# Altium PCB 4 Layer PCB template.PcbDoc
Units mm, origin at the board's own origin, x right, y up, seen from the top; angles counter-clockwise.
Board outline 100 x 100 mm, 4 copper layers (Top, Plane 1, Plane 2, Bottom), stack 1.506 mm thick; 2 components, 0 nets, 4 pads, 0 vias.
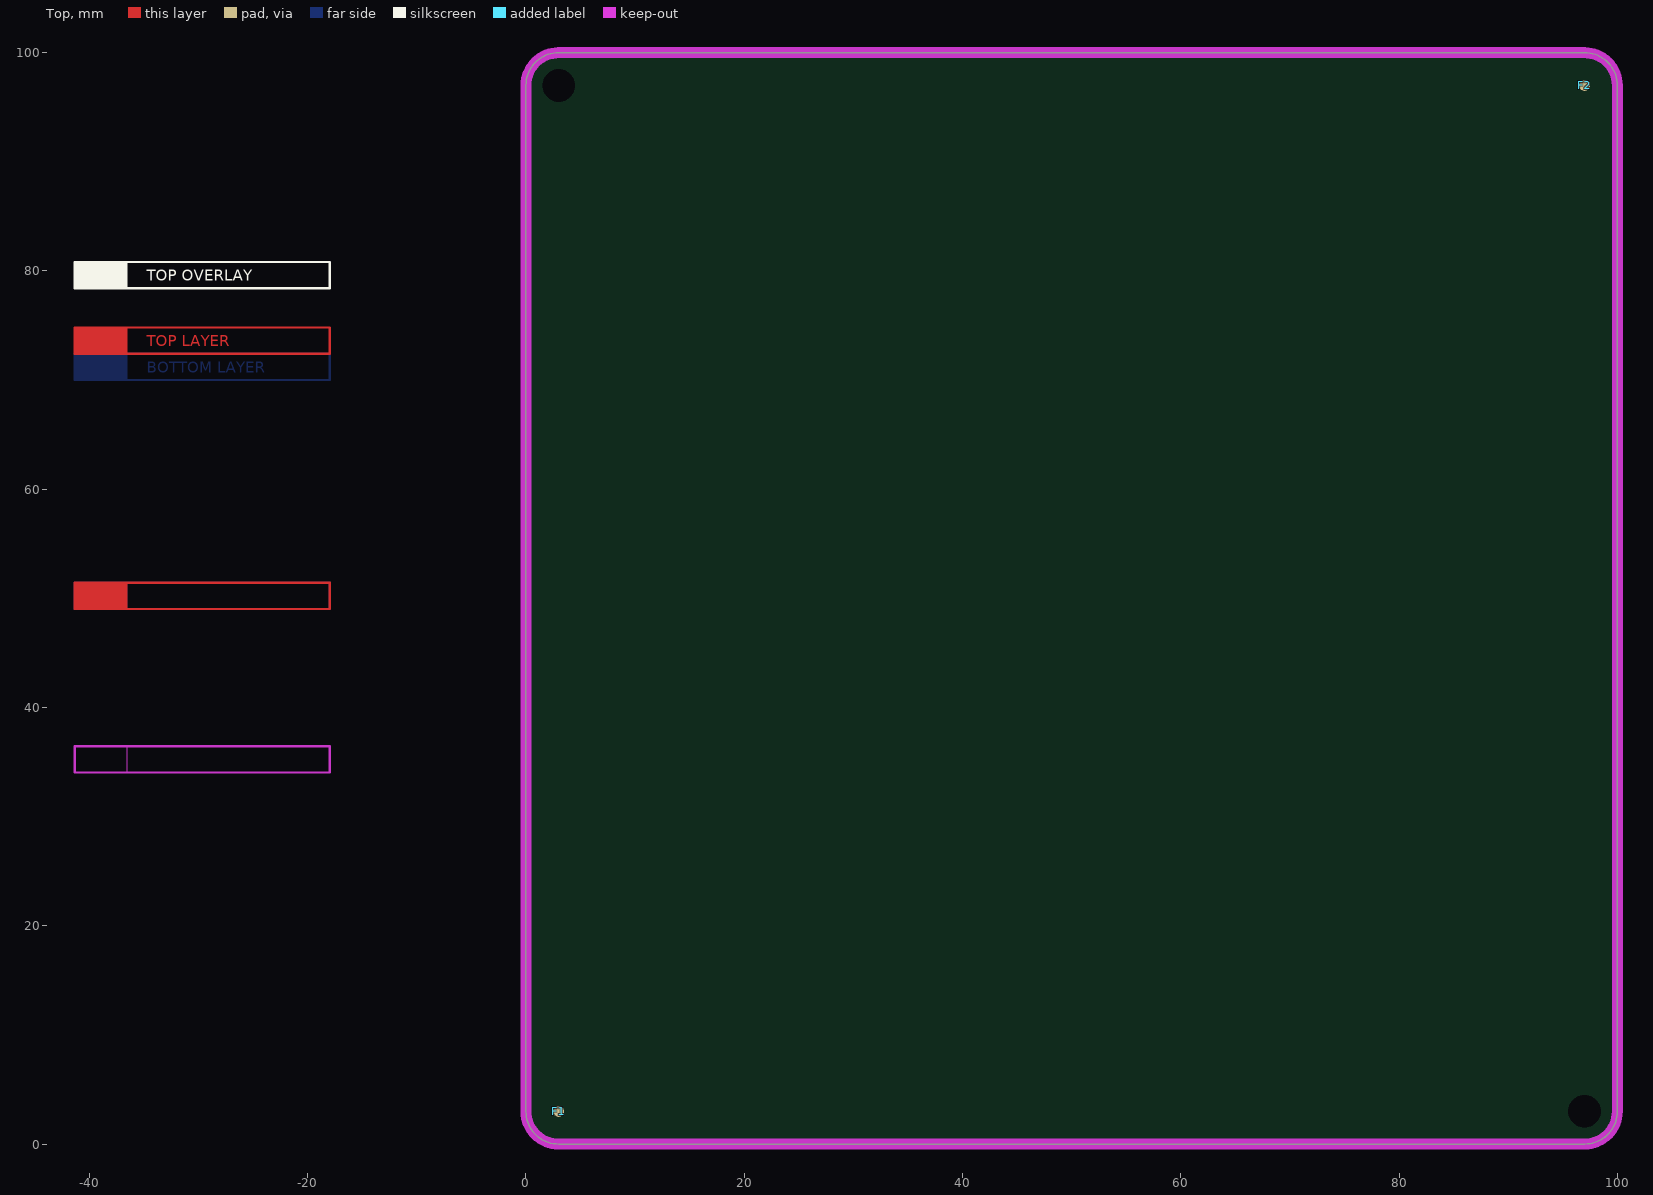
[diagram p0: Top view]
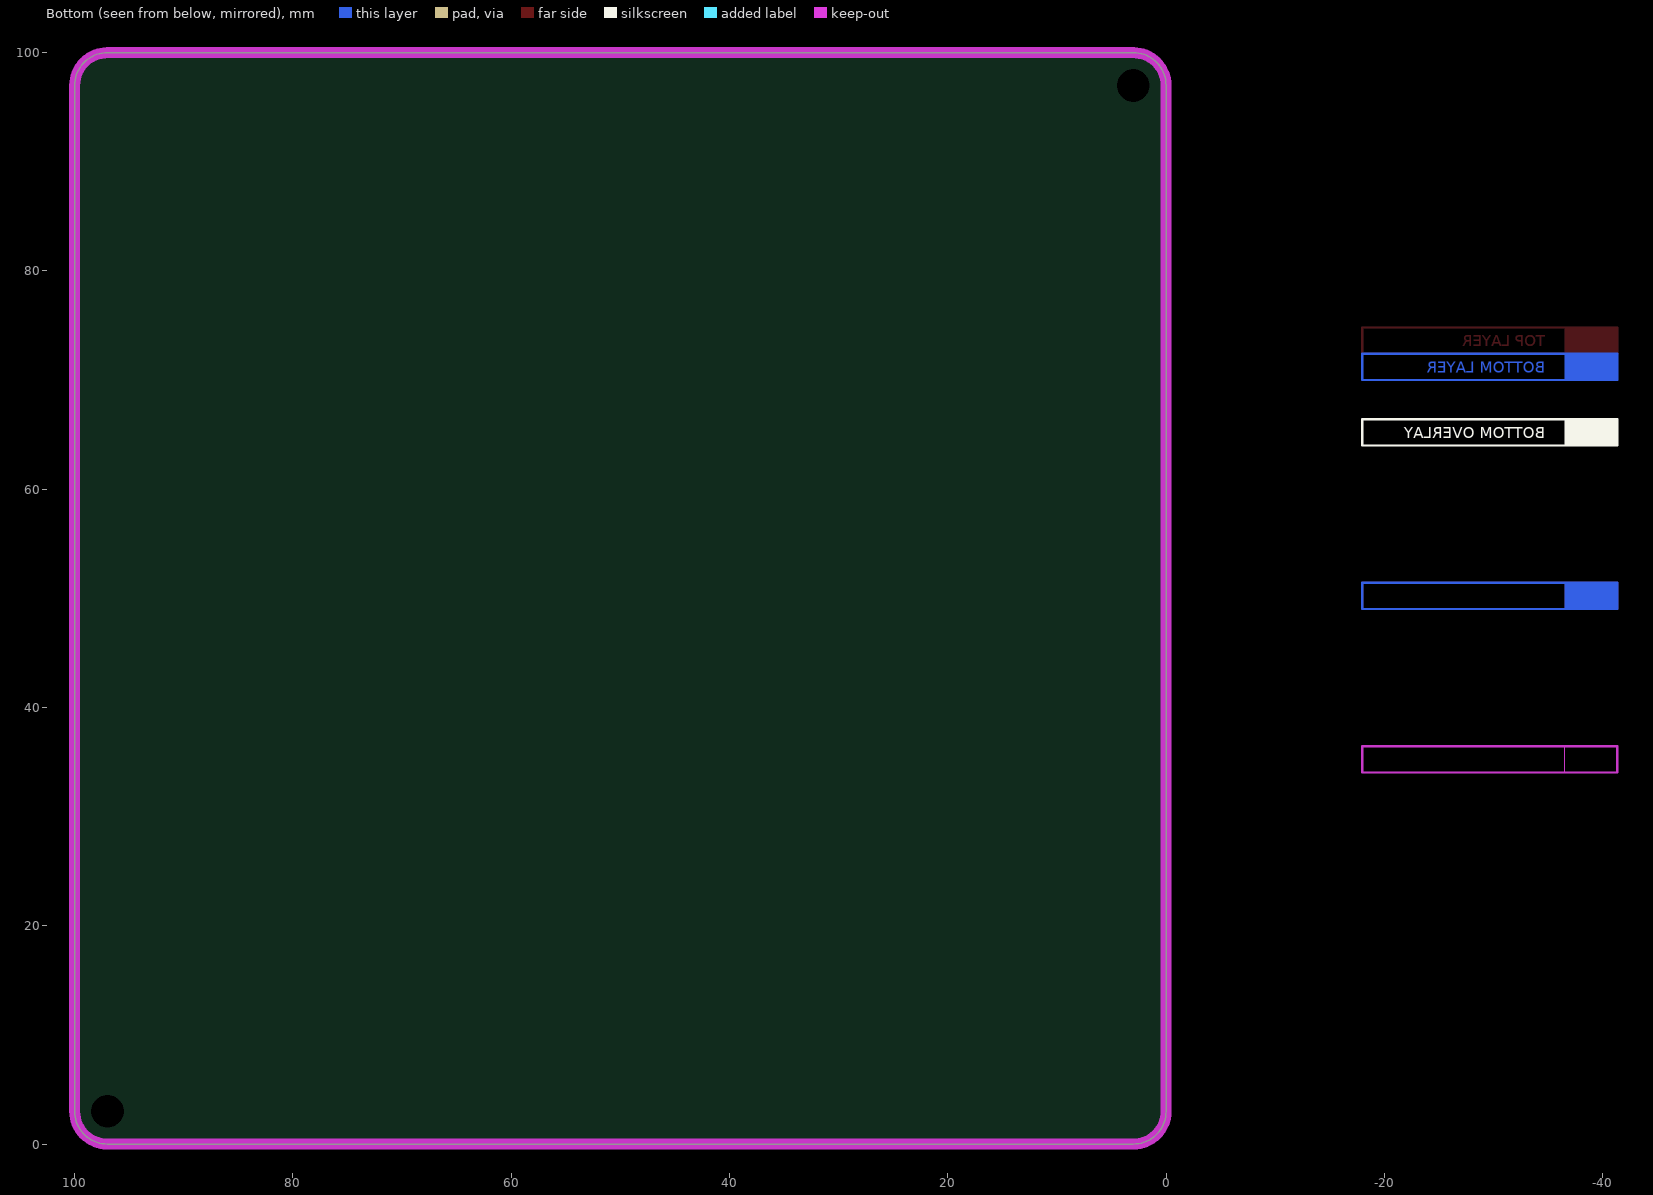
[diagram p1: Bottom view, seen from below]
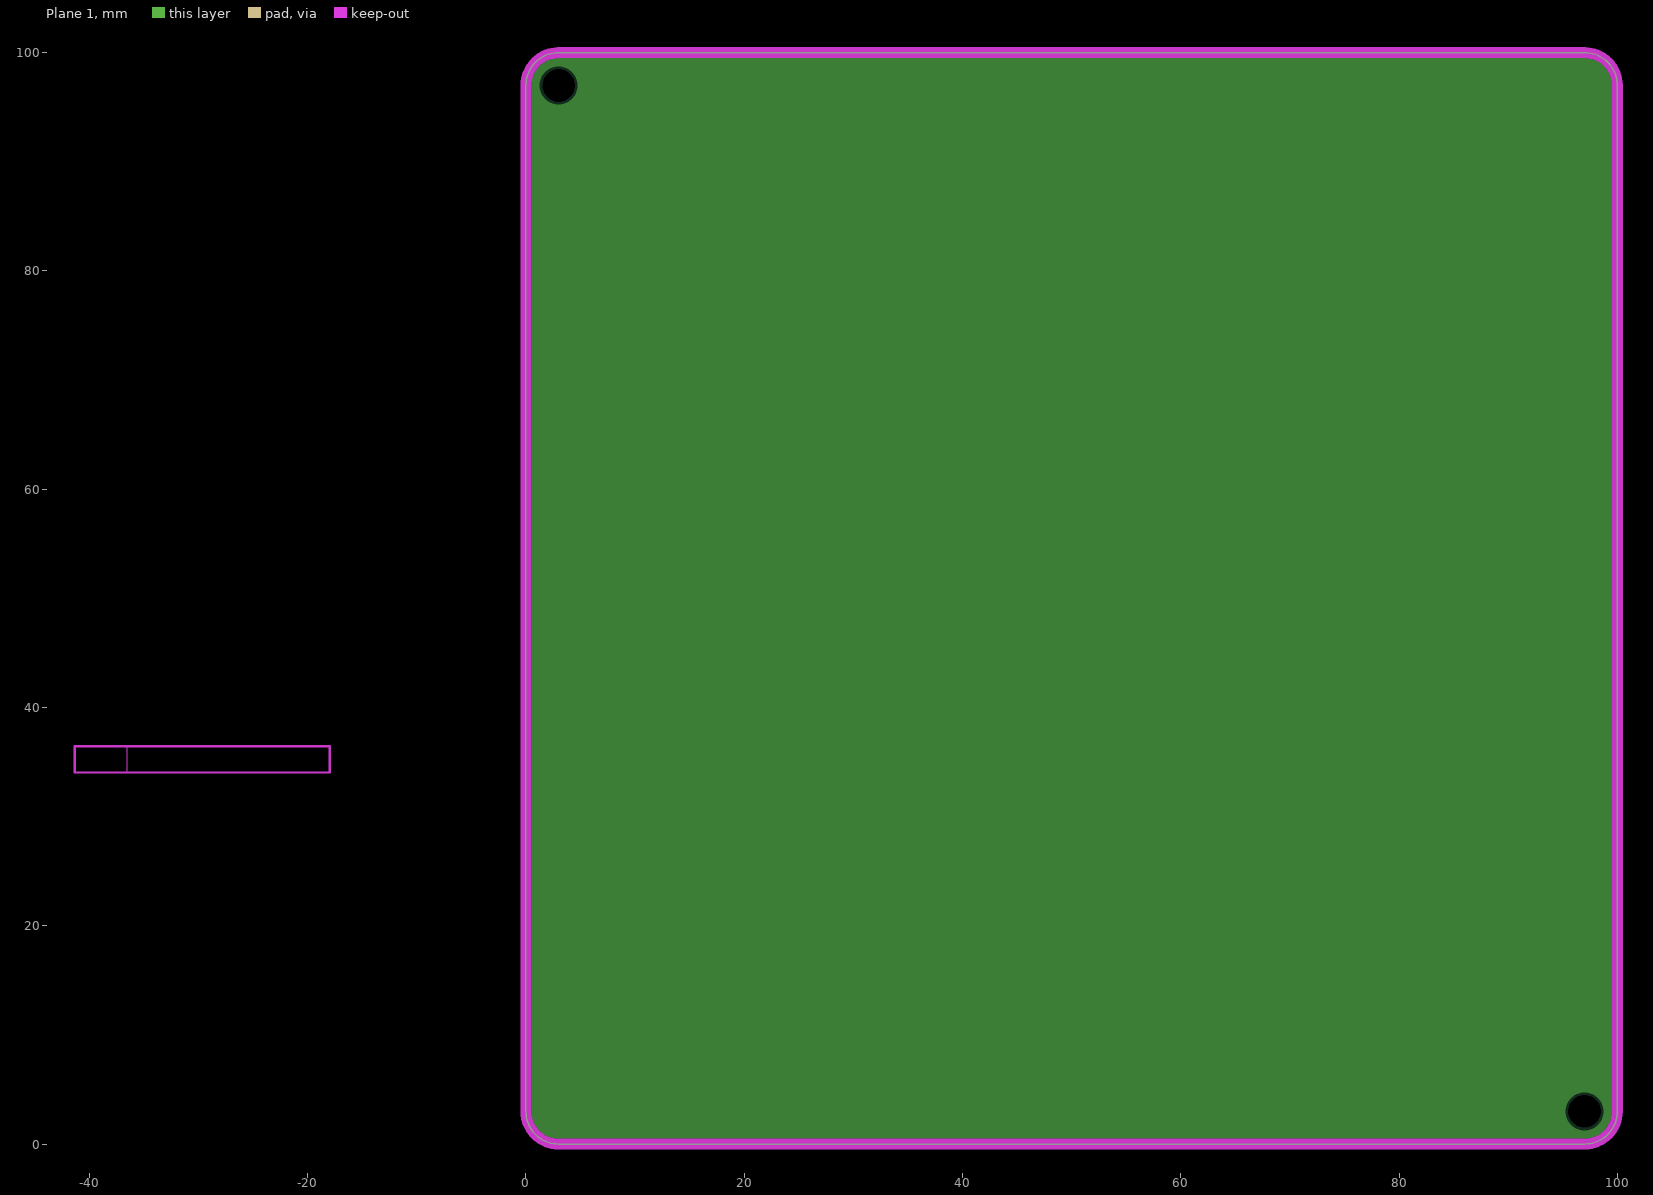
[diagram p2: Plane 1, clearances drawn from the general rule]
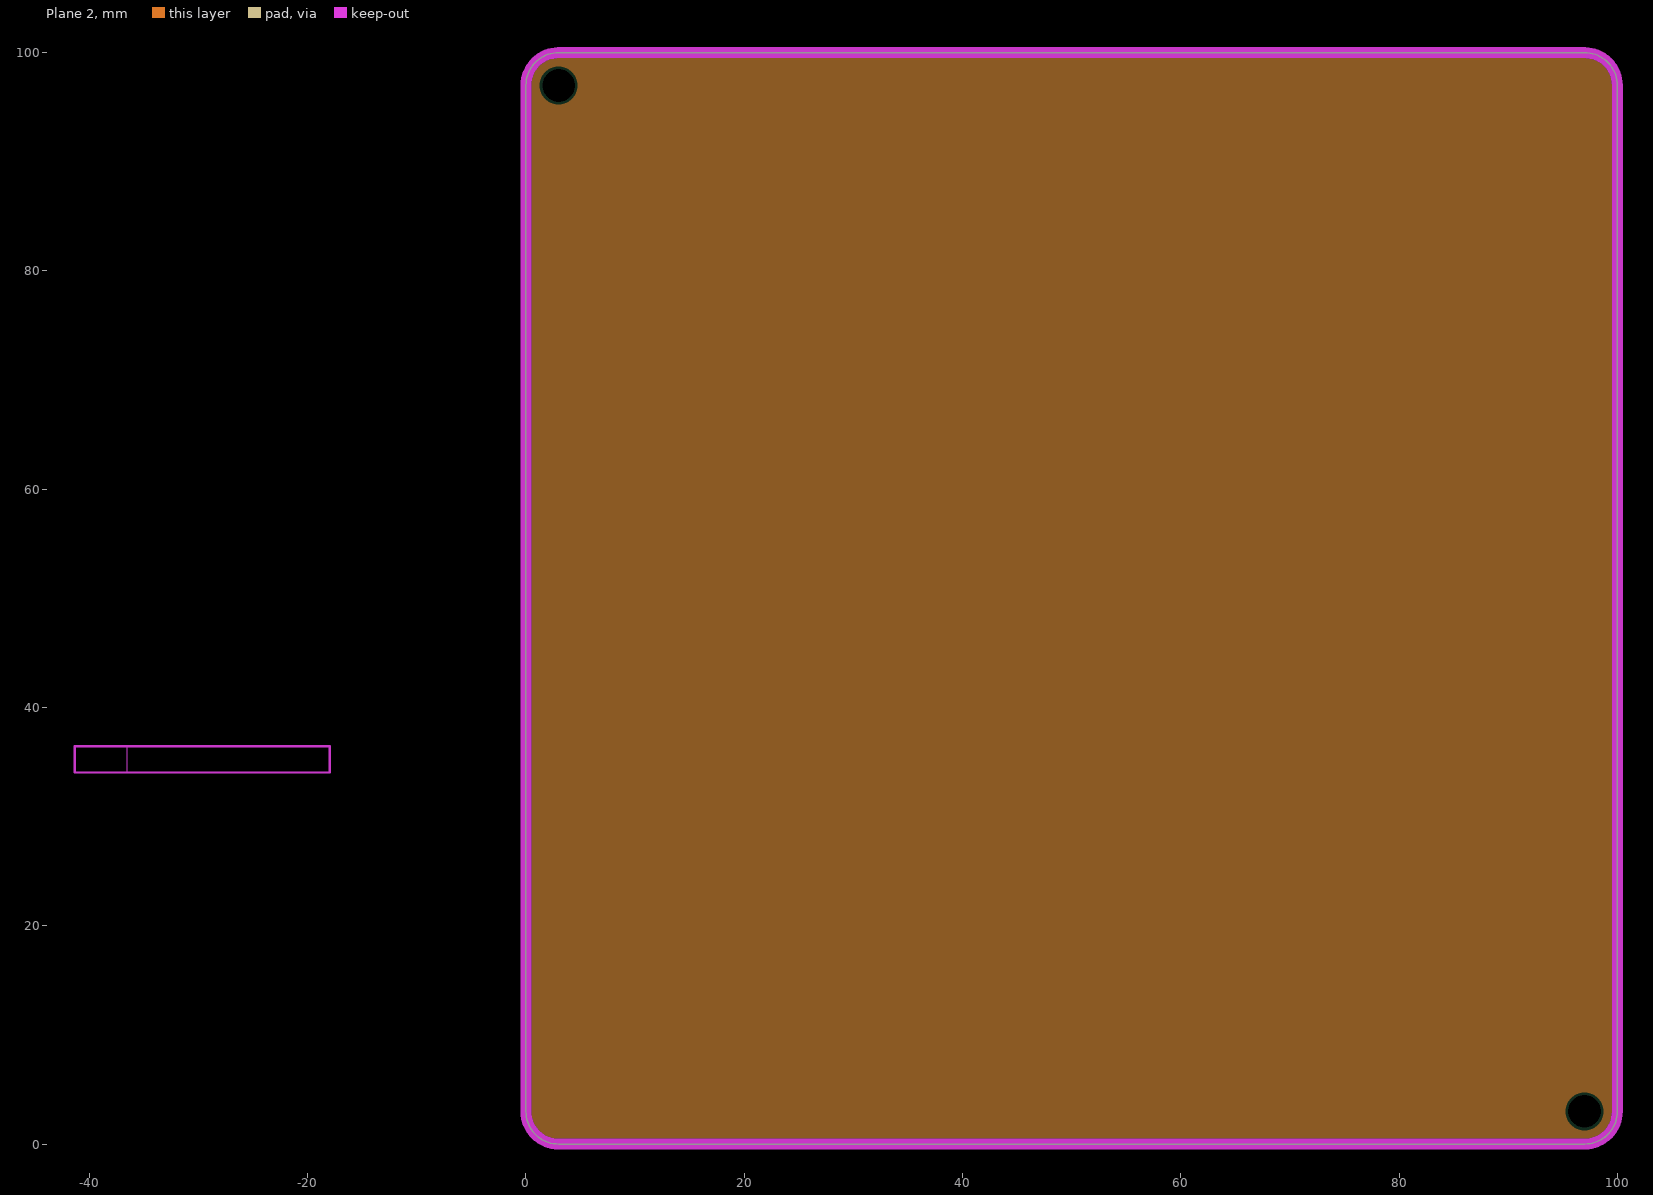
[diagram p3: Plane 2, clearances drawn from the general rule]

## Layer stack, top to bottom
Top: signal copper 0.035
Dielectric: core 0.2, FR-4, Dk 4.8
Plane 1: plane copper 0.018
Dielectric: prepreg 1, FR-4, Dk 4.8
Plane 2: plane copper 0.018
Dielectric: core 0.2, FR-4, Dk 4.8
Bottom: signal copper 0.035

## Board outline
0,3 0,97 cw(c3,97) 3,100 97,100 cw(c97,97) 100,97 100,3 cw(c97,3) 97,0 3,0 cw(c3,3)

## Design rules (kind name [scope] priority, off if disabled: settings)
AssemblyTestPointUsage [All] p1 off:
AssemblyTestpoint [All] p1 off: testpointundercomponent=TRUE minsize=1.016 maxsize=2.54 preferedsize=1.524 minholesize=0 maxholesize=1.016 preferedholesize=0.813 testpointgrid=0.025 usegrid=TRUE gridtolerance=0 allowsidetop=TRUE allowsidebottom=TRUE
Clearance ClearanceViaPad [IsVia vs IsPad] p1: gap=0.1
Clearance ClearanceGNDpolygons [InPolygonClass('GNDpolygons')] p2: gap=0.3
Clearance ClearanceTechnology [All] p3: gap=0.2
FabricationTestPointUsage [All] p1 off: valid=0 allowmultiple=FALSE
FabricationTestpoint [All] p1 off: side=3 testpointundercomponent=TRUE minsize=1.016 maxsize=2.54 preferedsize=1.524 minholesize=0 maxholesize=1.016 preferedholesize=0.813 testpointgrid=0.025 allowsidetop=TRUE allowsidebottom=TRUE usegrid=TRUE gridtolerance=0
HoleSize [All] p1: absolutevalues=TRUE maxlimit=6.3 minlimit=0.3 maxpercent=80.000 minpercent=20.000
HoleToHoleClearance [All] p1: gap=0.3 allowstackedmicrovias=TRUE
MinimumAnnularRing [All] p1: minimumring=0.2
MinimumSolderMaskSliver [All] p1: minsoldermaskwidth=0
PlaneClearance [All] p1: clearance=0.25
PlaneConnect [All] p1: planeconnectstyle=Relief reliefexpansion=0.508 reliefentries=4 reliefconductorwidth=0.254 reliefairgap=0.254
PolygonConnect PolygonConnectVia [IsVia] p1: connectstyle=Direct reliefconductorwidth=0.4 reliefentries=4 polygonreliefangle="90 Angle" airgapwidth=0.254
PolygonConnect PolygonConnectBigPads [(ObjectKind = 'Pad') And ((AsMM(PadXSize_AllLayers) > 2) Or (AsMM(PadYSize_AllLayers) > 2))] p2: connectstyle=Direct reliefconductorwidth=0.4 reliefentries=4 polygonreliefangle="90 Angle" airgapwidth=0.254
PolygonConnect PolygonConnectGeneral [All] p3: connectstyle=Relief reliefconductorwidth=0.3 reliefentries=4 polygonreliefangle="90 Angle" airgapwidth=0.2
RoutingVias [All] p1: holewidth=0.6 width=1.2 viastyle="Through Hole" minholewidth=0.3 minwidth=0.7 maxholewidth=0.9 maxwidth=1.4
SilkToSilkClearance [All] p1: silktosilkclearance=0.15
SilkToSolderMaskClearance SilkscreenOverComponentPads [IsPad] p1: minsilkscreentomaskgap=0.1 clearancetoexposedcopper=FALSE
SolderMaskExpansion [All] p1: expansion=0.1
Width WidthTechnology [All] p1: maxlimit=3 minlimit=0.16 preferedwidth=0.6 minimp=50.000000 maximp=50.000000 favimp=50.000000
17 further rules are at their usual default settings.

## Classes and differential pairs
channel class "Column driver": "U_Column driver 1" "U_Column driver 2" "U_Column driver 3" "U_Column driver 4"
channel class "Row driver": "U_Row driver 1" "U_Row driver 2" "U_Row driver 3" "U_Row driver 4" "U_Row driver 5" "U_Row driver 6" "U_Row driver 7" "U_Row driver 8"

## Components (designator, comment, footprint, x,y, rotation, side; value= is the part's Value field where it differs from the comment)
F1 "Fiducial" FIDUCIAL 3,3 r90 top locked
F2 "Fiducial" FIDUCIAL 97,97 r90 top locked

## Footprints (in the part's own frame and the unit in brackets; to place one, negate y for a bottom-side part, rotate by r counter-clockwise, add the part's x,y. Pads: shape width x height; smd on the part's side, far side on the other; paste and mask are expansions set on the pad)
FIDUCIAL [mm] "Fiducial"
  round 1 smd paste-1 mask+0.5: ""(0,0)
  body extent -0.49,-0.5 0.5,0.5, height 0.5

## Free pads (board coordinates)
  round 1 hole 3: 0(3,97) 0(97,3)

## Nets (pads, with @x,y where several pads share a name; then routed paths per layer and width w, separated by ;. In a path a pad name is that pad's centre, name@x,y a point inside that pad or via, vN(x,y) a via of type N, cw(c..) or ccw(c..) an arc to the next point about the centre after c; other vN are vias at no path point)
pads on no net: F1. F2.
copper on no net: | length 103.1
  Top w0.2: -41.342,72.414 -41.342,74.827 -17.974,74.827 -17.974,72.414 -41.342,72.414
  Bottom w0.2: -41.342,70.001 -41.342,72.414 -17.974,72.414 -17.974,70.001 -41.342,70.001

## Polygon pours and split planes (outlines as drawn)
no net on Plane 1 (split plane): 97.218,99.49 97.434,99.462 97.647,99.415 97.855,99.349 98.056,99.266 98.25,99.165 98.434,99.048 98.607,98.915 98.768,98.768 98.915,98.607 99.048,98.434 99.165,98.25 99.266,98.056 99.349,97.855 99.415,97.647 99.462,97.434 99.49,97.218 99.499,97.016 99.498,97 99.498,3 99.499,2.984 99.49,2.782 99.462,2.566 99.415,2.353 99.349,2.145 99.266,1.944 99.165,1.75 99.048,1.566 98.915,1.393 98.768,1.232 98.607,1.085 98.434,0.952 98.25,0.835 98.056,0.734 97.855,0.651 97.647,0.585 97.434,0.538 97.218,0.51 97.016,0.501 97,0.502 3,0.502 2.984,0.501 2.782,0.51 2.566,0.538 2.353,0.585 2.145,0.651 1.944,0.734 1.75,0.835 1.566,0.952 1.393,1.085 1.232,1.232 1.085,1.393 0.952,1.566 0.835,1.75 0.734,1.944 0.651,2.145 0.585,2.353 0.538,2.566 0.51,2.782 0.501,2.984 0.502,3 0.502,97 0.501,97.016 0.51,97.218 0.538,97.434 0.585,97.647 0.651,97.855 0.734,98.056 0.835,98.25 0.952,98.434 1.085,98.607 1.232,98.768 1.393,98.915 1.566,99.048 1.75,99.165 1.944,99.266 2.145,99.349 2.353,99.415 2.566,99.462 2.782,99.49 2.984,99.499 3,99.498 97,99.498 97.016,99.499
no net on Plane 2 (split plane): 97.218,99.49 97.434,99.462 97.647,99.415 97.855,99.349 98.056,99.266 98.25,99.165 98.434,99.048 98.607,98.915 98.768,98.768 98.915,98.607 99.048,98.434 99.165,98.25 99.266,98.056 99.349,97.855 99.415,97.647 99.462,97.434 99.49,97.218 99.499,97.016 99.498,97 99.498,3 99.499,2.984 99.49,2.782 99.462,2.566 99.415,2.353 99.349,2.145 99.266,1.944 99.165,1.75 99.048,1.566 98.915,1.393 98.768,1.232 98.607,1.085 98.434,0.952 98.25,0.835 98.056,0.734 97.855,0.651 97.647,0.585 97.434,0.538 97.218,0.51 97.016,0.501 97,0.502 3,0.502 2.984,0.501 2.782,0.51 2.566,0.538 2.353,0.585 2.145,0.651 1.944,0.734 1.75,0.835 1.566,0.952 1.393,1.085 1.232,1.232 1.085,1.393 0.952,1.566 0.835,1.75 0.734,1.944 0.651,2.145 0.585,2.353 0.538,2.566 0.51,2.782 0.501,2.984 0.502,3 0.502,97 0.501,97.016 0.51,97.218 0.538,97.434 0.585,97.647 0.651,97.855 0.734,98.056 0.835,98.25 0.952,98.434 1.085,98.607 1.232,98.768 1.393,98.915 1.566,99.048 1.75,99.165 1.944,99.266 2.145,99.349 2.353,99.415 2.566,99.462 2.782,99.49 2.984,99.499 3,99.498 97,99.498 97.016,99.499

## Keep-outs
Keep-Out Layer:
  rectangle: -41.342,34.035 -36.516,36.448
  lines w0.2: -41.342,34.035 -41.342,36.448 -17.974,36.448 -17.974,34.035 -41.342,34.035
  lines w1: 3,100 ccw(c3,97) 0,97 0,3 ccw(c3,3) 3,0 97,0 ccw(c97,3) 100,3 ; 3,100 3,100 ; 3,100 97,100 ; 97,100 cw(c97,97) 100,97 ; 97,100 97,100 ; 100,3 100,97 ; 100,3 100,3 ; 100,97 100,97
  text "ROUTING KEEPOUT LAYER" at -34.738,34.721 h0.89

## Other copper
Top:
  rectangle: -41.342,72.414 -36.516,74.827
  text "TOP LAYER" at -34.738,73.1 h1.02
Bottom:
  rectangle: -41.342,70.001 -36.516,72.414
  text "BOTTOM LAYER" at -34.738,70.687 h1.02
Multi-Layer:
  rectangle: -41.342,49.021 -36.516,51.434
  lines w0.2: -41.342,49.021 -41.342,51.434 -17.974,51.434 -17.974,49.021 -41.342,49.021
  text "MULTILAYER" at -34.738,49.707 h1.02

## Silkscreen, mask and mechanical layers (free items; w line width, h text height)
Top Overlay:
  rectangle: -41.342,78.409 -36.516,80.822
  lines w0.2: -41.342,78.409 -17.974,78.409 -17.974,80.822 -41.342,80.822 -41.342,78.409
  text "TOP OVERLAY" at -34.738,79.094 h1.02
Bottom Overlay:
  rectangle: -41.342,64.007 -36.516,66.42
  lines w0.2: -41.342,64.007 -17.974,64.007 -17.974,66.42 -41.342,66.42 -41.342,64.007
  text "BOTTOM OVERLAY" at -34.738,64.693 h1.02
Top Paste:
  rectangle: -41.342,81.406 -36.516,83.819
  lines w0.2: -41.342,81.406 -41.342,83.819 -17.974,83.819 -17.974,81.406 -41.342,81.406
  text "TOP PASTE" at -34.738,82.092 h1.02
Bottom Paste:
  rectangle: -41.342,61.01 -36.516,63.423
  lines w0.2: -41.342,61.01 -41.342,63.423 -17.974,63.423 -17.974,61.01 -41.342,61.01
  text "BOTTOM PASTE" at -34.738,61.695 h1.02
Top Solder:
  rectangle: -41.342,75.411 -36.516,77.824
  lines w0.2: -41.342,75.411 -17.974,75.411 -17.974,77.824 -41.342,77.824 -41.342,75.411
  text "TOP SOLDER MASK" at -34.738,76.097 h1.02
Bottom Solder:
  rectangle: -41.342,67.004 -36.516,69.417
  lines w0.2: -41.342,67.004 -41.342,69.417 -17.974,69.417 -17.974,67.004 -41.342,67.004
  text "BOTTOM SOLDER MASK" at -34.738,67.69 h1.02
Drill Guide:
  rectangle: -41.342,58.012 -36.516,60.425
  lines w0.2: -41.342,58.012 -17.974,58.012 -17.974,60.425 -41.342,60.425 -41.342,58.012
  text "DRILL GUIDE (SLOTS)" at -34.738,58.698 h1.02
Outline:
  rectangle: -41.342,52.018 -36.516,54.431
  lines w0.1: 0,3 ccw(c3,3) 3,0 97,0 ccw(c97,3) 100,3 100,97 ccw(c97,97) 97,100 3,100 ccw(c3,97) 0,97 0,3
  lines w0.2: -41.342,52.018 -17.974,52.018 -17.974,54.431 -41.342,54.431 -41.342,52.018
  lines w0.25: 123.924,-23.15 253.976,-23.15 ; 123.924,-19.005 253.976,-19.005 ; 122.4,-49.75 ccw(c123.75,-49.75) 123.75,-51.1 254.15,-51.1 ccw(c254.15,-49.75) 255.5,-49.75 255.5,-15.35 ccw(c254.15,-15.35) 254.15,-14 123.75,-14 ccw(c123.75,-15.35) 122.4,-15.35 122.4,-49.75
  lines w0.254: -43.882,117.702 69,117.702 69,112 ; -43.882,122.827 69,122.827 69,117.136 ; -39.056,86.105 -19.498,86.105 ; 33,112 33,117.702 ; 69,122.825 94.975,122.825 ; -43.882,31.825 -43.882,91.693 -15.18,91.693 -15.18,31.825 -43.882,31.825 ; -43.882,112 -43.882,130.05 95,130.05 95,112 -43.882,112
  text ".GlobalProjectName" at -32.125,124.975 h3
  text "Project:" at -42.406,124.816 h1.2
  text ".GlobalProjectTeam" at -34.65,119.3 h2.03
  text ".GlobalProjectLink" at 35.15,119.3 h2.03
  text "Team:" at -42.406,119.225 h1.2
  text "More info:" at 25.35,119.225 h1.2
  text ".GlobalProjectRevision" at 75,114 h7
  text ".Pcb_File_Name_No_Path" at -28,113.934 h2.03
  text "PCB file name:" at -42.406,113.907 h1.2
  text ".GlobalRevisionDate" at 48.119,113.507 h2.03
  text "Rev:" at 71,113.507 h1.2
  text "Revision date:" at 34.944,113.407 h1.2
  text "LAYER USAGE" at -39.056,86.816 h2.03
  text "Fusion service size limits" at 131,77 h5
  text "5cm X 5cm" at 134,72.002 h5
  text "5cm X 10cm" at 134,68.224 h5
  text "5cm X 15cm" at 134,64.446 h5
  text "5cm X 20cm" at 134,60.668 h5
  text "10cm X 10cm" at 134,56.89 h5
  text "10cm X 15cm" at 134,53.112 h5
  text "BOARD OUTLINE" at -34.738,52.704 h1.02
  text "10cm X 20cm" at 134,49.334 h5
  text "15cm X 15cm" at 134,45.556 h5
  text "15cm X 20cm" at 134,41.778 h5
  text "20cm X 20cm" at 134,38 h5
  text "Set Net names for internal plane layers in Design » Layer Stack Manager" at 124,12 h5
  text "Layer Stack Up Detail for: 4 Layer Seed Fusion template.PcbDoc" at 123.924,-17.898 h1.9
  text "Layer" at 123.924,-20.555 h0.95
  text "Gerber" at 151.492,-20.555 h0.95
  text "Copper" at 165.787,-20.555 h0.95
  text "Dielectric" at 181.634,-20.555 h0.95
  text "Dielectric" at 198.146,-20.555 h0.95
  text "Dielectric" at 218.966,-20.555 h0.95
  text "Dielectric" at 235.477,-20.555 h0.95
  text "Name" at 123.924,-22.455 h0.95
  text "Document" at 151.492,-22.455 h0.95
  text "Thickness" at 165.787,-22.455 h0.95
  text "Height" at 181.634,-22.455 h0.95
  text "Material" at 198.146,-22.455 h0.95
  text "Constant" at 218.966,-22.455 h0.95
  text "Type" at 235.477,-22.455 h0.95
  text "Top Solder Mask" at 123.924,-25.207 h1.35
  text "(.GTS)" at 151.492,-25.207 h1.35
  text "0.0102mm" at 181.634,-25.207 h1.35
  text "Solder Resist" at 198.146,-25.207 h1.35
  text "3.50" at 218.966,-25.207 h1.35
  text "Top" at 123.924,-29.072 h1.35
  text "(.GTL)" at 151.492,-29.072 h1.35
  text "0.035mm" at 165.787,-29.072 h1.35
  text "0.2mm" at 181.634,-31.004 h1.35
  text "FR-4" at 198.146,-31.004 h1.35
  text "4.80" at 218.966,-31.004 h1.35
  text "Core" at 235.477,-31.004 h1.35
  text "Plane 1" at 123.924,-32.936 h1.35
  text "(.GP1)" at 151.492,-32.936 h1.35
  text "0.018mm" at 165.787,-32.936 h1.35
  text "1mm" at 181.634,-34.869 h1.35
  text "FR-4" at 198.146,-34.869 h1.35
  text "4.80" at 218.966,-34.869 h1.35
  text "PrePreg" at 235.477,-34.869 h1.35
  text "Plane 2" at 123.924,-36.801 h1.35
  text "(.GP2)" at 151.492,-36.801 h1.35
  text "0.018mm" at 165.787,-36.801 h1.35
  text "0.2mm" at 181.634,-38.733 h1.35
  text "FR-4" at 198.146,-38.733 h1.35
  text "4.80" at 218.966,-38.733 h1.35
  text "Core" at 235.477,-38.733 h1.35
  text "Bottom" at 123.924,-40.666 h1.35
  text "(.GBL)" at 151.492,-40.666 h1.35
  text "0.035mm" at 165.787,-40.666 h1.35
  text "Bottom Solder Mask" at 123.924,-44.53 h1.35
  text "(.GBS)" at 151.492,-44.53 h1.35
  text "0.0102mm" at 181.634,-44.53 h1.35
  text "Solder Resist" at 198.146,-44.53 h1.35
  text "3.50" at 218.966,-44.53 h1.35
Dimensions:
  rectangle: -41.342,37.032 -36.516,39.445
  lines w0.2: -41.146,-10.834 -23.061,-10.834 ; -41.07,-2.782 -22.985,-2.782 ; -41.07,16.369 -22.985,16.369 ; -41.045,8.673 -22.96,8.673 ; -40.918,19.798 -22.833,19.798 ; -41.342,37.032 -17.974,37.032 -17.974,39.445 -41.342,39.445 -41.342,37.032
  lines w0.254: -42.064,-17.8 -42.064,23.583 -17.908,23.583 -17.908,-17.8 -42.064,-17.8
  text "DIMENSIONS" at -34.738,37.718 h1.02
  text "BUILD STATISTICS" at -40.816,20.586 h1.52
  text "GENERAL" at -41.019,16.877 h1.02
  text ".Net_Count" at -31.342,14.769 h1.02
  text "NETS" at -40.943,14.718 h0.89
  text ".Component_Count" at -31.342,12.686 h1.02
  text "COMPONENTS" at -40.918,12.661 h0.89
  text "PRIMITIVES" at -40.994,9.181 h1.02
  text ".Fill_Count" at -31.342,7.048 h1.02
  text "FILLS" at -40.918,7.022 h0.89
  text ".Track_Count" at -31.342,4.99 h1.02
  text "TRACKS" at -40.918,4.939 h0.89
  text ".String_Count" at -31.342,2.907 h1.02
  text "STRINGS" at -40.918,2.857 h0.89
  text ".Arc_Count" at -31.342,0.799 h1.02
  text "ARC'S" at -40.918,0.748 h0.89
  text "LANDS" at -41.019,-2.274 h1.02
  text ".Pad_Count" at -31.342,-4.408 h1.02
  text ".Pad_Count" at -31.342,-4.408 h1.02
  text "PADS" at -40.918,-4.459 h0.89
  text ".Via_Count" at -31.342,-6.491 h1.02
  text "VIA'S" at -40.892,-6.516 h0.89
  text "PRINT SCALE" at -41.095,-10.326 h1.02
  text ".Print_Scale" at -31.393,-12.485 h1.02
  text "SCALE" at -40.968,-12.51 h0.89
  text ".Print_Date" at -31.393,-14.542 h1.02
  text "PRINT DATE" at -40.943,-14.568 h0.89
  text ".Print_Time" at -31.367,-16.6 h1.02
  text "PRINT TIME" at -40.918,-16.625 h0.89
Assembly Top:
  rectangle: -41.342,46.024 -36.516,48.437
  lines w0.2: -41.342,46.024 -41.342,48.437 -17.974,48.437 -17.974,46.024 -41.342,46.024
  text "TOP ASSEMBLY" at -34.738,46.709 h1.02
Assembly Bot:
  rectangle: -41.342,43.026 -36.516,45.439
  lines w0.2: -41.342,43.026 -41.342,45.439 -17.974,45.439 -17.974,43.026 -41.342,43.026
  text "BOTTOM ASSEMBLY" at -34.738,43.712 h1.02
Drill Drawing:
  rectangle: -41.342,55.015 -36.516,57.428
  lines w0.025: -0.319,-43.866 0.316,-43.548 0.951,-43.866 0.633,-43.231 0.951,-42.596 0.316,-42.913 -0.319,-42.596 -0.002,-43.231 -0.319,-43.866
  lines w0.2: -41.342,55.015 -41.342,57.428 -17.974,57.428 -17.974,55.015 -41.342,55.015
  lines w0.381: -2.05,-45.009 96.476,-45.009 ; -2.05,-41.199 96.476,-41.199 ; 11.943,-48.819 11.943,-37.389 ; 29.667,-48.819 29.667,-37.389 ; 63.846,-48.819 63.846,-37.389 ; 76.695,-48.819 76.695,-37.389 ; -2.05,-48.819 96.476,-48.819 96.476,-37.389 -2.05,-37.389 -2.05,-48.819
  text "DRILL DRAWING" at -34.738,55.701 h1.02
  text "Symbol" at 0.236,-40.056 h1.83
  text "Hit Count" at 13.086,-40.056 h1.83
  text "Finished Hole Size" at 30.81,-40.056 h1.83
  text "Plated" at 64.989,-40.056 h1.83
  text "Hole Type" at 77.838,-40.056 h1.83
  text "2" at 13.086,-43.866 h1.52
  text "3.0mm" at 30.81,-43.866 h1.52
  text "PTH" at 64.989,-43.866 h1.52
  text "Round" at 77.838,-43.866 h1.52
  text "2 Total" at 13.086,-47.676 h1.52

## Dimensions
97,0 to 97,100 on Dimensions
0,3 to 100,3 on Dimensions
